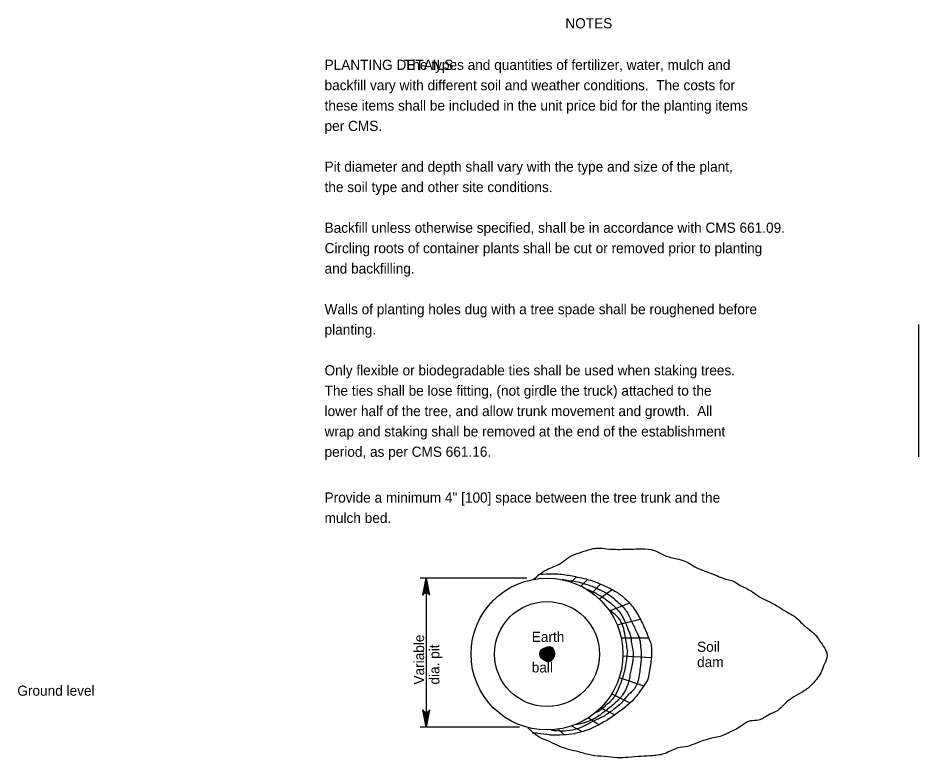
# Model space of a CAD drawing. Extents: x 3862.5 to 3891, y 3400.3 to 3419.7.
# Drawn here: x 3876.81 to 3889.19, y 3409.52 to 3419.69 of the extents above; entities that cross this region are included whole.
import ezdxf

# ---------------------------------------------------------------- set-up
doc = ezdxf.new("R2010")
doc.units = 0
doc.layers.add('DR_X_Trench_Drain', color=7, linetype='Continuous')
doc.layers.add('GT_X_Coal_Seam_1', color=7, linetype='Continuous')

msp = doc.modelspace()

# ---------------------------------------------------------------- linework, layer by layer
msp.add_lwpolyline([(3889.186, 3413.657), (3889.186, 3415.477)])
at = {"layer": 'DR_X_Trench_Drain'}
for p, q in [((3884.405, 3411.935), (3884.474, 3412.004)), ((3884.541, 3411.879), (3884.633, 3411.97)), ((3884.694, 3411.786), (3884.808, 3411.907)), ((3884.791, 3411.705), (3884.968, 3411.831)), ((3884.934, 3411.539), (3885.203, 3411.647)), ((3885.039, 3411.347), (3885.355, 3411.425)), ((3885.095, 3411.169), (3885.469, 3411.17)), ((3883.988, 3410.974), (3884.068, 3410.856)), ((3883.989, 3410.974), (3884.069, 3410.857)), ((3883.99, 3410.975), (3884.07, 3410.857)), ((3883.993, 3410.977), (3884.073, 3410.859)), ((3883.994, 3410.978), (3884.074, 3410.86)), ((3883.995, 3410.979), (3884.075, 3410.861)), ((3883.996, 3410.98), (3884.076, 3410.862)), ((3883.997, 3410.98), (3884.077, 3410.863)), ((3883.997, 3410.98), (3884.077, 3410.862)), ((3883.999, 3410.982), (3884.079, 3410.864)), ((3883.999, 3410.981), (3884.079, 3410.863)), ((3884.001, 3410.983), (3884.081, 3410.865)), ((3884.001, 3410.983), (3884.081, 3410.865)), ((3884.002, 3410.983), (3884.082, 3410.865)), ((3884.003, 3410.984), (3884.083, 3410.866)), ((3884.003, 3410.984), (3884.083, 3410.867)), ((3884.004, 3410.985), (3884.084, 3410.867)), ((3884.005, 3410.986), (3884.085, 3410.868)), ((3884.006, 3410.986), (3884.086, 3410.868)), ((3884.006, 3410.986), (3884.086, 3410.868)), ((3884.007, 3410.987), (3884.087, 3410.869)), ((3884.007, 3410.987), (3884.088, 3410.869)), ((3884.009, 3410.989), (3884.089, 3410.871)), ((3884.01, 3410.989), (3884.09, 3410.871)), ((3884.01, 3410.989), (3884.09, 3410.871)), ((3884.011, 3410.99), (3884.091, 3410.872)), ((3884.013, 3410.991), (3884.093, 3410.873)), ((3884.014, 3410.992), (3884.094, 3410.874)), ((3884.015, 3410.992), (3884.095, 3410.874)), ((3884.017, 3410.994), (3884.097, 3410.876)), ((3884.019, 3410.995), (3884.099, 3410.877)), ((3884.019, 3410.995), (3884.099, 3410.877)), ((3884.022, 3410.997), (3884.102, 3410.879)), ((3884.022, 3410.997), (3884.102, 3410.879)), ((3884.022, 3410.997), (3884.102, 3410.879)), ((3884.024, 3410.998), (3884.104, 3410.88)), ((3884.025, 3410.999), (3884.105, 3410.881)), ((3884.026, 3411), (3884.106, 3410.882)), ((3884.028, 3411.002), (3884.108, 3410.884)), ((3884.028, 3411.001), (3884.108, 3410.884)), ((3884.029, 3411.002), (3884.109, 3410.884)), ((3884.031, 3411.003), (3884.111, 3410.885)), ((3884.033, 3411.005), (3884.113, 3410.887)), ((3884.035, 3411.006), (3884.115, 3410.888)), ((3884.035, 3411.006), (3884.115, 3410.888)), ((3884.037, 3411.008), (3884.117, 3410.89)), ((3884.037, 3411.007), (3884.117, 3410.89)), ((3884.037, 3411.007), (3884.117, 3410.889)), ((3884.038, 3411.008), (3884.118, 3410.89)), ((3884.039, 3411.008), (3884.119, 3410.891)), ((3884.041, 3411.01), (3884.121, 3410.892)), ((3884.043, 3411.012), (3884.123, 3410.894)), ((3884.045, 3411.013), (3884.126, 3410.895)), ((3884.045, 3411.012), (3884.125, 3410.895)), ((3884.045, 3411.012), (3884.125, 3410.895)), ((3884.046, 3411.013), (3884.126, 3410.895)), ((3884.048, 3411.015), (3884.128, 3410.897)), ((3884.048, 3411.015), (3884.128, 3410.897)), ((3884.049, 3411.016), (3884.129, 3410.898)), ((3884.049, 3411.015), (3884.129, 3410.898)), ((3884.051, 3411.017), (3884.131, 3410.899)), ((3884.051, 3411.017), (3884.131, 3410.899)), ((3884.052, 3411.017), (3884.132, 3410.899)), ((3884.053, 3411.018), (3884.133, 3410.9)), ((3884.055, 3411.019), (3884.135, 3410.901)), ((3884.056, 3411.02), (3884.136, 3410.903)), ((3884.057, 3411.021), (3884.137, 3410.903)), ((3884.057, 3411.021), (3884.137, 3410.903)), ((3884.058, 3411.022), (3884.138, 3410.904)), ((3884.058, 3411.021), (3884.138, 3410.904)), ((3884.059, 3411.022), (3884.139, 3410.905)), ((3884.06, 3411.023), (3884.14, 3410.905)), ((3884.062, 3411.024), (3884.142, 3410.907)), ((3884.062, 3411.024), (3884.142, 3410.906)), ((3884.062, 3411.024), (3884.142, 3410.907)), ((3884.063, 3411.025), (3884.143, 3410.907)), ((3884.065, 3411.026), (3884.145, 3410.908)), ((3884.065, 3411.026), (3884.145, 3410.908)), ((3884.068, 3411.029), (3884.148, 3410.911)), ((3884.069, 3411.029), (3884.149, 3410.911)), ((3884.07, 3411.03), (3884.15, 3410.912)), ((3884.072, 3411.031), (3884.152, 3410.913)), ((3884.074, 3411.033), (3884.154, 3410.915)), ((3884.074, 3411.032), (3884.154, 3410.914)), ((3884.075, 3411.033), (3884.155, 3410.915)), ((3884.077, 3411.034), (3884.157, 3410.916)), ((3884.078, 3411.035), (3884.158, 3410.917)), ((3884.078, 3411.035), (3884.158, 3410.918)), ((3884.08, 3411.037), (3884.16, 3410.919)), ((3884.08, 3411.036), (3884.16, 3410.918)), ((3884.081, 3411.037), (3884.161, 3410.919)), ((3884.082, 3411.038), (3884.162, 3410.92)), ((3884.084, 3411.04), (3884.164, 3410.922)), ((3884.085, 3411.04), (3884.165, 3410.922)), ((3884.086, 3411.041), (3884.166, 3410.923)), ((3884.088, 3411.042), (3884.168, 3410.924)), ((3884.09, 3411.043), (3884.17, 3410.925)), ((3884.093, 3411.046), (3884.173, 3410.928)), ((3884.093, 3411.045), (3884.173, 3410.927)), ((3884.094, 3411.046), (3884.174, 3410.928)), ((3884.095, 3411.047), (3884.175, 3410.929)), ((3884.096, 3411.047), (3884.176, 3410.93)), ((3884.097, 3411.048), (3884.177, 3410.93)), ((3884.099, 3411.049), (3884.179, 3410.931)), ((3884.102, 3411.051), (3884.182, 3410.934)), ((3883.981, 3410.97), (3884.061, 3410.852)), ((3883.981, 3410.97), (3884.061, 3410.852)), ((3883.982, 3410.97), (3884.062, 3410.852)), ((3883.982, 3410.97), (3884.062, 3410.852)), ((3883.983, 3410.971), (3884.063, 3410.853)), ((3883.985, 3410.972), (3884.065, 3410.854)), ((3883.986, 3410.972), (3884.066, 3410.855)), ((3883.986, 3410.972), (3884.066, 3410.855)), ((3885.119, 3410.923), (3885.509, 3410.898)), ((3885.068, 3410.621), (3885.404, 3410.51)), ((3884.965, 3410.398), (3885.205, 3410.279)), ((3884.815, 3410.207), (3885.007, 3410.111)), ((3884.646, 3410.07), (3884.785, 3409.975)), ((3884.228, 3409.912), (3884.306, 3409.838)), ((3884.412, 3409.956), (3884.547, 3409.883))]:
    msp.add_line(p, q, dxfattribs=at)
for radius in [1.044, 0.721]:
    msp.add_circle((3884.075, 3410.945), radius, dxfattribs=at)
for points in [[(3883.885, 3411.968), (3884.067, 3412.104), (3884.264, 3412.195), (3884.357, 3412.263), (3884.599, 3412.364), (3884.768, 3412.403), (3884.896, 3412.392), (3885.048, 3412.385), (3885.165, 3412.386), (3885.295, 3412.391), (3885.378, 3412.394), (3885.546, 3412.37), (3885.692, 3412.301), (3885.858, 3412.256), (3885.971, 3412.223), (3886.115, 3412.141), (3886.261, 3412.079), (3886.392, 3412.03), (3886.494, 3411.987), (3886.646, 3411.941), (3886.73, 3411.888), (3886.85, 3411.83), (3886.98, 3411.742), (3887.114, 3411.672), (3887.235, 3411.607), (3887.35, 3411.535), (3887.5, 3411.443), (3887.579, 3411.365), (3887.699, 3411.265), (3887.787, 3411.177), (3887.854, 3411.079), (3887.913, 3410.977), (3887.926, 3410.921), (3887.888, 3410.813), (3887.838, 3410.689), (3887.777, 3410.597), (3887.692, 3410.504), (3887.562, 3410.41), (3887.438, 3410.338), (3887.351, 3410.27), (3887.261, 3410.182), (3887.118, 3410.107), (3886.982, 3410.036), (3886.868, 3410.025), (3886.698, 3409.925), (3886.615, 3409.885), (3886.501, 3409.829), (3886.318, 3409.782), (3886.129, 3409.72), (3886.004, 3409.675), (3885.873, 3409.654), (3885.701, 3409.58), (3885.528, 3409.547), (3885.366, 3409.538), (3885.19, 3409.525), (3885.041, 3409.518), (3884.861, 3409.536), (3884.687, 3409.553), (3884.512, 3409.599), (3884.371, 3409.634), (3884.244, 3409.679), (3884.118, 3409.736), (3884.024, 3409.774), (3883.947, 3409.815), (3883.866, 3409.88), (3883.809, 3409.93)], [(3884.618, 3411.974), (3884.493, 3412), (3884.305, 3412.034), (3884.091, 3412.043), (3883.955, 3412.034)], [(3884.282, 3411.974), (3884.653, 3411.892), (3884.813, 3411.823), (3884.934, 3411.756), (3885.038, 3411.67), (3885.157, 3411.547), (3885.233, 3411.401), (3885.301, 3411.261), (3885.348, 3411.144), (3885.36, 3411.045)], [(3884.618, 3411.974), (3884.725, 3411.942), (3884.876, 3411.878), (3885.026, 3411.801), (3885.15, 3411.706), (3885.263, 3411.58), (3885.32, 3411.495), (3885.405, 3411.323), (3885.458, 3411.203), (3885.504, 3411.068), (3885.509, 3410.898), (3885.48, 3410.693), (3885.456, 3410.588), (3885.392, 3410.492)], [(3884.577, 3411.856), (3884.812, 3411.744), (3884.932, 3411.659), (3885.04, 3411.56), (3885.12, 3411.444), (3885.183, 3411.301), (3885.226, 3411.175), (3885.23, 3411.112)], [(3885.179, 3410.995), (3885.151, 3411.193), (3885.055, 3411.445), (3884.923, 3411.552)], [(3885.23, 3411.112), (3885.257, 3410.968), (3885.223, 3410.698), (3885.185, 3410.528), (3885.121, 3410.396), (3885.094, 3410.358)], [(3884.062, 3411.035), (3883.991, 3410.994), (3883.97, 3410.937), (3884.02, 3410.874), (3884.099, 3410.843), (3884.172, 3410.905), (3884.178, 3410.973), (3884.14, 3411.035), (3884.063, 3411.035)], [(3884.061, 3411.032), (3883.992, 3410.993), (3883.973, 3410.937), (3884.021, 3410.876), (3884.099, 3410.845), (3884.17, 3410.906), (3884.176, 3410.972), (3884.138, 3411.033), (3884.064, 3411.033)], [(3884.061, 3411.033), (3883.992, 3410.993), (3883.973, 3410.937), (3884.021, 3410.876), (3884.099, 3410.845), (3884.17, 3410.906), (3884.176, 3410.972), (3884.138, 3411.033), (3884.064, 3411.033)], [(3884.059, 3411.027), (3883.996, 3410.99), (3883.977, 3410.938), (3884.024, 3410.879), (3884.098, 3410.85), (3884.166, 3410.908), (3884.172, 3410.971), (3884.136, 3411.029), (3884.067, 3411.029)], [(3884.059, 3411.024), (3883.997, 3410.989), (3883.979, 3410.938), (3884.025, 3410.881), (3884.098, 3410.852), (3884.164, 3410.909), (3884.17, 3410.971), (3884.135, 3411.028), (3884.067, 3411.027)], [(3884.058, 3411.021), (3883.999, 3410.987), (3883.982, 3410.939), (3884.027, 3410.883), (3884.097, 3410.855), (3884.162, 3410.91), (3884.168, 3410.97), (3884.134, 3411.025), (3884.069, 3411.025)], [(3884.057, 3411.016), (3884.002, 3410.985), (3883.986, 3410.939), (3884.029, 3410.886), (3884.097, 3410.859), (3884.158, 3410.912), (3884.164, 3410.97), (3884.132, 3411.022), (3884.071, 3411.021)], [(3884.056, 3411.014), (3884.004, 3410.983), (3883.988, 3410.94), (3884.03, 3410.887), (3884.096, 3410.861), (3884.157, 3410.913), (3884.162, 3410.969), (3884.131, 3411.02), (3884.072, 3411.019)], [(3884.056, 3411.012), (3884.005, 3410.982), (3883.99, 3410.94), (3884.031, 3410.888), (3884.096, 3410.863), (3884.155, 3410.913), (3884.161, 3410.969), (3884.13, 3411.018), (3884.073, 3411.018)], [(3884.055, 3411.01), (3884.006, 3410.981), (3883.991, 3410.94), (3884.031, 3410.889), (3884.096, 3410.864), (3884.154, 3410.914), (3884.159, 3410.968), (3884.129, 3411.017), (3884.073, 3411.017)], [(3884.054, 3411.004), (3884.009, 3410.978), (3883.996, 3410.941), (3884.034, 3410.893), (3884.095, 3410.869), (3884.15, 3410.916), (3884.155, 3410.967), (3884.127, 3411.013), (3884.076, 3411.012)], [(3884.052, 3411), (3884.012, 3410.976), (3884, 3410.942), (3884.036, 3410.896), (3884.094, 3410.873), (3884.147, 3410.918), (3884.152, 3410.967), (3884.125, 3411.009), (3884.078, 3411.009)], [(3884.052, 3410.999), (3884.012, 3410.976), (3884, 3410.942), (3884.036, 3410.896), (3884.094, 3410.873), (3884.146, 3410.918), (3884.151, 3410.967), (3884.125, 3411.009), (3884.078, 3411.009)], [(3884.05, 3410.989), (3884.019, 3410.971), (3884.009, 3410.943), (3884.041, 3410.902), (3884.093, 3410.882), (3884.139, 3410.922), (3884.143, 3410.965), (3884.121, 3411.001), (3884.082, 3411.001)], [(3884.049, 3410.988), (3884.019, 3410.97), (3884.01, 3410.943), (3884.042, 3410.903), (3884.093, 3410.883), (3884.138, 3410.922), (3884.143, 3410.965), (3884.12, 3411.001), (3884.082, 3411)], [(3884.049, 3410.988), (3884.019, 3410.971), (3884.009, 3410.943), (3884.041, 3410.903), (3884.093, 3410.883), (3884.139, 3410.922), (3884.143, 3410.965), (3884.12, 3411.001), (3884.082, 3411.001)], [(3884.049, 3410.986), (3884.02, 3410.97), (3884.011, 3410.943), (3884.042, 3410.904), (3884.092, 3410.884), (3884.137, 3410.923), (3884.142, 3410.964), (3884.12, 3411), (3884.083, 3410.999)], [(3884.021, 3410.969), (3884.012, 3410.944), (3884.043, 3410.905), (3884.092, 3410.886), (3884.136, 3410.923), (3884.14, 3410.964), (3884.119, 3410.998), (3884.084, 3410.998)], [(3884.027, 3410.964), (3884.02, 3410.945), (3884.047, 3410.911), (3884.091, 3410.894), (3884.13, 3410.927), (3884.133, 3410.962), (3884.115, 3410.991), (3884.088, 3410.991)], [(3885.179, 3410.995), (3885.163, 3410.843), (3885.117, 3410.634), (3885.054, 3410.464), (3884.939, 3410.286), (3884.889, 3410.247)], [(3885.36, 3411.045), (3885.37, 3410.909), (3885.355, 3410.754), (3885.32, 3410.557), (3885.237, 3410.424), (3885.189, 3410.383)], [(3885.392, 3410.492), (3885.308, 3410.371), (3885.04, 3410.131), (3884.742, 3409.949), (3884.464, 3409.855), (3884.458, 3409.854)], [(3885.189, 3410.383), (3885.1, 3410.276), (3884.968, 3410.166), (3884.832, 3410.078), (3884.712, 3410.021), (3884.563, 3409.945), (3884.278, 3409.885), (3884.135, 3409.894)], [(3885.094, 3410.358), (3885.017, 3410.28), (3884.892, 3410.174), (3884.757, 3410.077), (3884.703, 3410.045)], [(3884.744, 3410.141), (3884.82, 3410.185), (3884.889, 3410.247)], [(3884.703, 3410.045), (3884.664, 3410.027), (3884.465, 3409.971)], [(3884.109, 3409.836), (3883.947, 3409.854), (3883.876, 3409.859)], [(3884.109, 3409.836), (3884.296, 3409.837), (3884.458, 3409.854)]]:
    msp.add_spline(points, degree=3, dxfattribs=at)
at = {"layer": 'GT_X_Coal_Seam_1'}
for p, q in [((3883.798, 3411.99), (3882.332, 3411.99)), ((3882.382, 3411.774), (3882.415, 3411.99)), ((3882.396, 3411.782), (3882.415, 3411.99)), ((3882.415, 3411.99), (3882.415, 3410.791)), ((3882.415, 3411.786), (3882.415, 3411.99)), ((3882.43, 3411.783), (3882.415, 3411.99)), ((3882.445, 3411.776), (3882.415, 3411.99)), ((3882.415, 3410.791), (3882.415, 3409.941)), ((3882.385, 3410.155), (3882.415, 3409.941)), ((3882.4, 3410.147), (3882.415, 3409.941)), ((3882.448, 3410.157), (3882.415, 3409.941)), ((3882.434, 3410.149), (3882.415, 3409.941)), ((3882.415, 3410.145), (3882.415, 3409.941)), ((3883.698, 3409.941), (3882.332, 3409.941))]:
    msp.add_line(p, q, dxfattribs=at)
for points in [[(3882.368, 3411.754), (3882.415, 3411.99), (3882.462, 3411.754)], [(3882.462, 3410.177), (3882.415, 3409.941), (3882.368, 3410.177)]]:
    msp.add_lwpolyline(points, dxfattribs=at)
for centre, start, end in [((3882.415, 3411.735), 22.0878, 157.9139), ((3882.415, 3410.196), 202.0878, 337.9139)]:
    msp.add_arc(centre, 0.051, start, end, dxfattribs=at)

# ---------------------------------------------------------------- texts
for s, p in [('NOTES', (3884.327, 3419.548)), ('PLANTING DETAILS:', (3881.018, 3418.977)), ('                     The types and quantities of fertilizer, water, mulch and', (3881.018, 3418.977)), ('backfill vary with different soil and weather conditions.  The costs for', (3881.018, 3418.697)), ('these items shall be included in the unit price bid for the planting items', (3881.018, 3418.417)), ('per CMS. ', (3881.018, 3418.137)), ('Pit diameter and depth shall vary with the type and size of the plant,', (3881.018, 3417.577)), ('the soil type and other site conditions.', (3881.018, 3417.297)), ('Backfill unless otherwise specified, shall be in accordance with CMS 661.09.', (3881.018, 3416.737)), ('Circling roots of container plants shall be cut or removed prior to planting', (3881.018, 3416.457)), ('and backfilling.', (3881.018, 3416.177)), ('Walls of planting holes dug with a tree spade shall be roughened before', (3881.018, 3415.617)), ('planting.', (3881.018, 3415.337)), ('Only flexible or biodegradable ties shall be used when staking trees.', (3881.018, 3414.777)), ('The ties shall be lose fitting, (not girdle the truck) attached to the ', (3881.018, 3414.497)), ('lower half of the tree, and allow trunk movement and growth.  All', (3881.018, 3414.217)), ('wrap and staking shall be removed at the end of the establishment ', (3881.018, 3413.937)), ('period, as per CMS 661.16.', (3881.018, 3413.657)), ('Provide a minimum 4" [100] space between the tree trunk and the', (3881.018, 3413.027)), ('mulch bed.', (3881.018, 3412.747)), ('Earth', (3883.865, 3411.112)), ('Soil', (3886.137, 3410.976)), ('dam', (3886.137, 3410.766)), ('ball', (3883.865, 3410.692)), ('Ground level', (3876.796, 3410.372))]:
    msp.add_text(s, height=0.14, dxfattribs=at).set_placement(p)
for s, p in [('Variable', (3882.386, 3410.526)), ('dia. pit', (3882.596, 3410.526))]:
    msp.add_text(s, height=0.14, rotation=90, dxfattribs=at).set_placement(p)

doc.saveas('drawing.dxf')
